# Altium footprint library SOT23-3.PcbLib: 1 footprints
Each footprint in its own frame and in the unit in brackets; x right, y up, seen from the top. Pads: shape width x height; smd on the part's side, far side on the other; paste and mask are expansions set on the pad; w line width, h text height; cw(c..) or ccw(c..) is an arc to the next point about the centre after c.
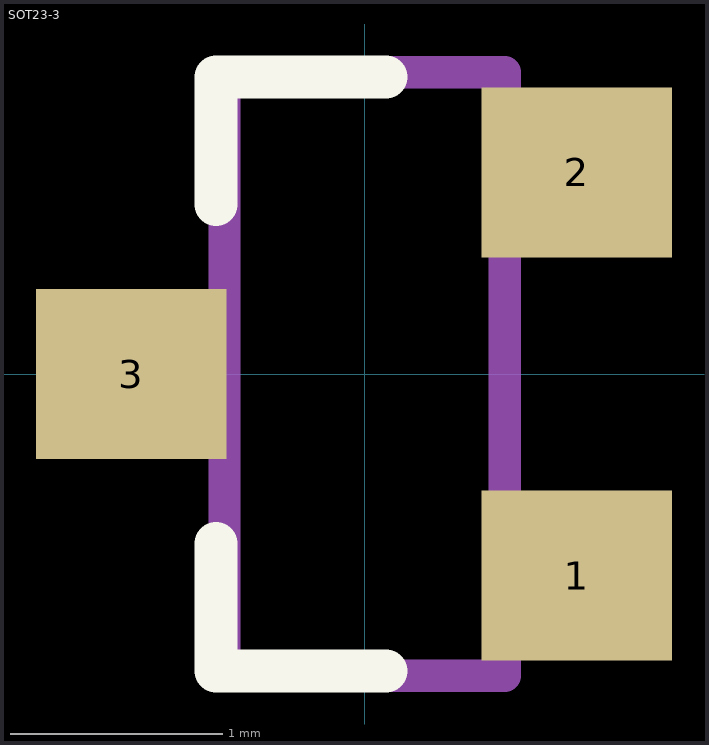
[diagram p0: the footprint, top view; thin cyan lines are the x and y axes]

## SOT23-3 [mm]
pads (3):
  rect 0.9x0.8 smd: 1(1,-0.95) 2(1,0.95) 3(-1.1,0)
Top Overlay:
  lines w0.203: -0.7,-0.8 -0.7,-1.4 0.1,-1.4 ; -0.7,0.8 -0.7,1.4 0.1,1.4
Mechanical 13:
  lines w0.152: -0.66,-1.422 -0.66,1.422 0.66,1.422 0.66,-1.422 -0.66,-1.422
3D body "step_temp.STEP": height 1.25, standoff 0, extent -1.4,-1.45 1.4,1.45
